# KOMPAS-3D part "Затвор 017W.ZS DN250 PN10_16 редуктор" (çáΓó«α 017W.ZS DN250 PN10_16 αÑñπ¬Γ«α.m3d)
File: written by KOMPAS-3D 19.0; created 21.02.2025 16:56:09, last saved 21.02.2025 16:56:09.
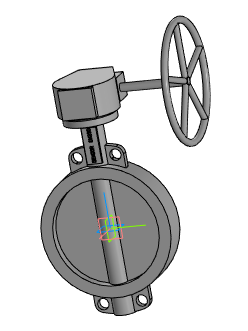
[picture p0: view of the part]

Document properties: Автор: Евгений; Полное имя файла: Затвор 017W.ZS DN250 PN10_16 редуктор.a3d

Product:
- Part/product: Затвор 017W.ZS DN250 PN10_16 редуктор
    Масса: 41.6148

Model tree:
1. Операция без истории:1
